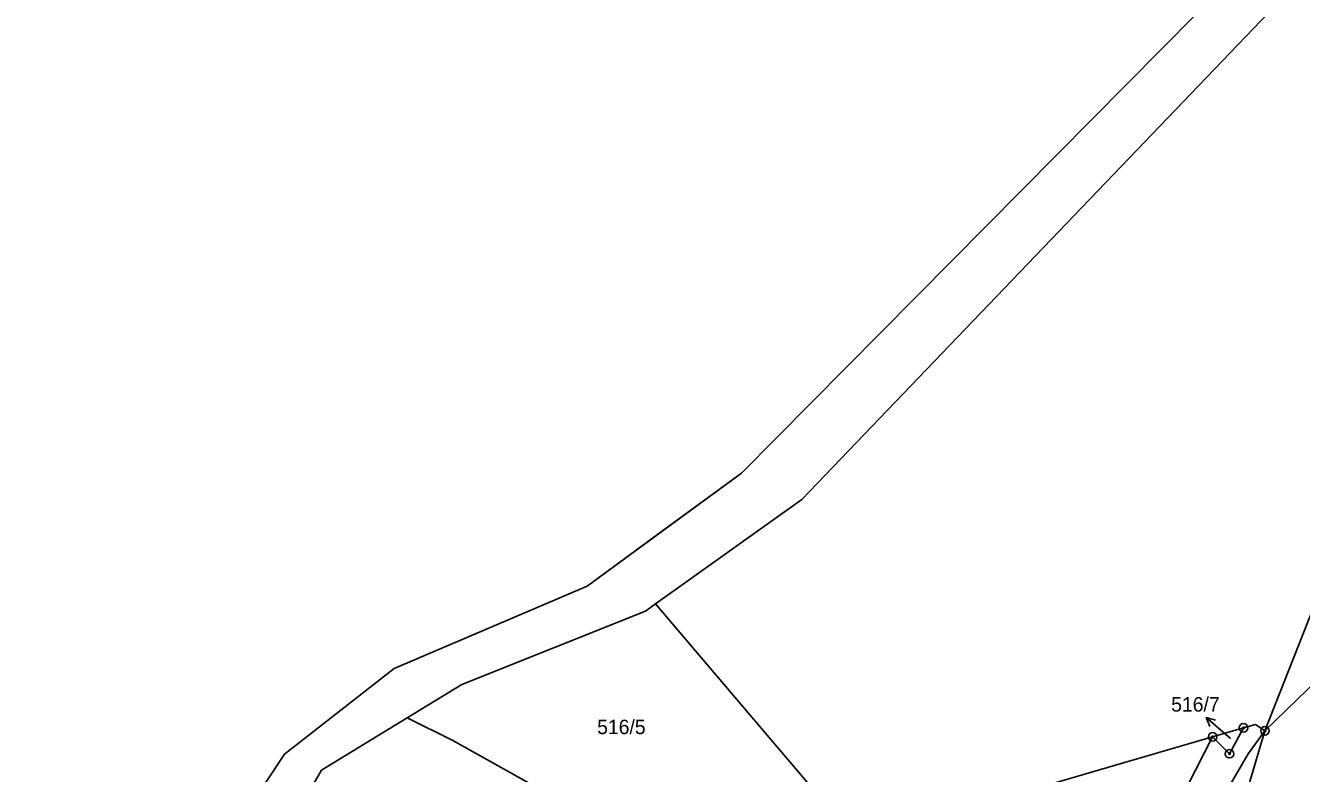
# Model space of a CAD drawing. Extents: x -547623 to -538651, y -1096714 to -1086522.
# Drawn here: x -546878.5 to -546728.6, y -1094028.5 to -1093940.6 of the extents above; entities that cross this region are included whole.
import ezdxf

# ---------------------------------------------------------------- set-up
doc = ezdxf.new("R2010")
doc.units = 0
for name, color, linetype in [('podzemní_provozovana', 7, 'Continuous'), ('Vrstva 1', 7, 'Continuous'), ('Vrstva 41', 7, 'Continuous'), ('Vrstva 52', 7, 'Continuous'), ('Vrstva 83', 7, 'Continuous'), ('Vrstva 86', 7, 'Continuous')]:
    doc.layers.add(name, color=color, linetype=linetype)

msp = doc.modelspace()

# ---------------------------------------------------------------- linework, layer by layer
at = {"layer": 'podzemní_provozovana'}
msp.add_line((-546737.47, -1094023.9), (-546739.74, -1094021.94), dxfattribs=at)
for points in [[(-546739.31, -1094022.97), (-546739.74, -1094021.94), (-546738.66, -1094022.22)], [(-546736.91, -1094024.38), (-546737.47, -1094023.9)]]:
    msp.add_lwpolyline(points, dxfattribs=at)
at = {"layer": 'Vrstva 1'}
for points in [[(-546730.56, -1093937.09), (-546787.26, -1093996.29)], [(-546787.26, -1093996.29), (-546804.44, -1094008.58)], [(-546732.85, -1094023.5), (-546708.98, -1094000.34)], [(-546732.85, -1094023.5), (-546724.94, -1094003.44)], [(-546805.61, -1094009.42), (-546827.21, -1094018.04)], [(-546804.44, -1094008.58), (-546805.61, -1094009.42)], [(-546775.55, -1094042.57), (-546804.44, -1094008.58)], [(-546827.21, -1094018.04), (-546833.62, -1094021.95)], [(-546833.62, -1094021.95), (-546843.7, -1094028.1)], [(-546828.24, -1094024.61), (-546833.62, -1094021.95)], [(-546735.36, -1094023.14), (-546738.99, -1094024.2)], [(-546737.01, -1094026.18), (-546735.36, -1094023.14)], [(-546733.95, -1094022.73), (-546735.36, -1094023.14)], [(-546732.85, -1094023.5), (-546733.95, -1094022.73)], [(-546813.35, -1094032.96), (-546828.24, -1094024.61)], [(-546738.99, -1094024.2), (-546764.63, -1094031.69)], [(-546752.62, -1094050.92), (-546738.99, -1094024.2)], [(-546738.99, -1094024.2), (-546737.01, -1094026.18)], [(-546737.21, -1094038.23), (-546732.85, -1094023.5)], [(-546734.83, -1094026.21), (-546732.85, -1094023.5)], [(-546745.13, -1094043.86), (-546734.83, -1094026.21)], [(-546843.7, -1094028.1), (-546847.29, -1094034.38)]]:
    msp.add_lwpolyline(points, dxfattribs=at)
at = {"layer": 'Vrstva 41'}
msp.add_line((-546740.87, -1093939.19), (-546794.34, -1093993.21), dxfattribs=at)
for points in [[(-546794.34, -1093993.21), (-546812.47, -1094006.47)], [(-546835.14, -1094016.17), (-546812.47, -1094006.47)], [(-546835.14, -1094016.17), (-546848.05, -1094026.22)], [(-546848.05, -1094026.22), (-546858.66, -1094042.25)]]:
    msp.add_lwpolyline(points, dxfattribs=at)
at = {"layer": 'Vrstva 52'}
msp.add_lwpolyline([(-546882.33, -1094148.69), (-546881.59, -1094143.97), (-546880.71, -1094135.77), (-546881.61, -1094129.26), (-546882.76, -1094120.96), (-546879.79, -1094111.89), (-546878.22, -1094107.1), (-546878.16, -1094100.74), (-546875.2, -1094083.45), (-546874.97, -1094082.12), (-546874.65, -1094081.34), (-546858.66, -1094042.25), (-546848.05, -1094026.22), (-546835.14, -1094016.17), (-546812.47, -1094006.47), (-546803.62, -1094000), (-546794.34, -1093993.21), (-546740.87, -1093939.19)], dxfattribs=at)
at = {"layer": 'Vrstva 83'}
for centre, radius in [((-546735.36, -1094023.14), 0.5), ((-546735.36, -1094023.14), 0.1), ((-546732.85, -1094023.5), 0.5), ((-546738.99, -1094024.2), 0.5), ((-546738.99, -1094024.2), 0.1), ((-546732.85, -1094023.5), 0.1), ((-546737.01, -1094026.18), 0.5), ((-546737.01, -1094026.18), 0.1)]:
    msp.add_circle(centre, radius, dxfattribs=at)

# ---------------------------------------------------------------- texts
at = {"layer": 'podzemní_provozovana'}
msp.add_text('516/7', height=1.7, dxfattribs=at).set_placement((-546743.86, -1094021.23))
at = {"layer": 'Vrstva 86'}
for s, height, p in [('516/5', 1.7, (-546811.3, -1094023.88)), ('516/7', 0.1, (-546737.08, -1094024.38))]:
    msp.add_text(s, height=height, dxfattribs=at).set_placement(p)

doc.saveas('drawing.dxf')
